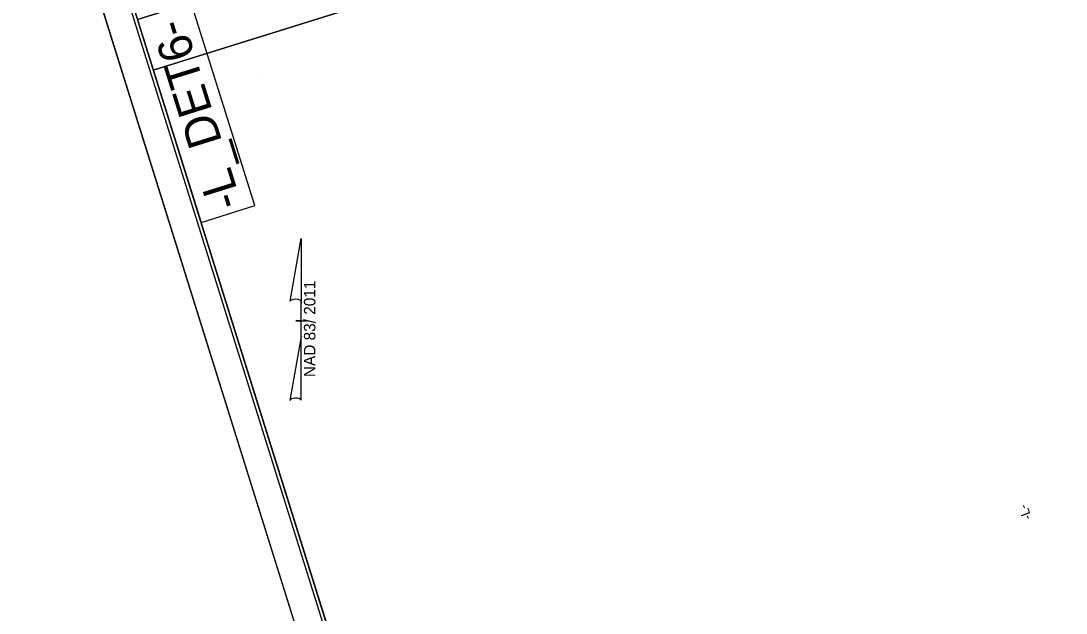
# Model space of a CAD drawing. Extents: x 473667 to 478950, y 494687 to 505998.
# Drawn here: x 473667 to 474441, y 505031 to 505469 of the extents above; entities that cross this region are included whole.
import ezdxf

# ---------------------------------------------------------------- set-up
doc = ezdxf.new("R2010")
doc.units = 0
for name, color, linetype in [('Old_Level_1', 7, 'Continuous'), ('Prop Grid Mask', 7, 'Continuous'), ('Prop Horizontal Alignment Tick Label', 7, 'Continuous'), ('Prop North Arrow NAD83 for Plan Sheets CELL', 7, 'Continuous'), ('Sheet Cutting Line CELL', 7, 'Continuous'), ('Sheet Layout Plan Border', 7, 'Continuous'), ('Sheet North Arrow Point CELL', 7, 'Continuous'), ('Sheet Plan CELL', 7, 'Continuous'), ('Sheet Plan Layout CELL', 7, 'Continuous'), ('Sheet Plot Border Inside CELL', 7, 'Continuous'), ('Sheet Plot Border Outside CELL', 7, 'Continuous')]:
    doc.layers.add(name, color=color, linetype=linetype)

msp = doc.modelspace()

# ---------------------------------------------------------------- linework, layer by layer
at = {"layer": 'Prop Grid Mask'}
msp.add_lwpolyline([(473753.52, 505469.97), (473800.56, 505319.8), (473840.36, 505332.27), (473793.32, 505482.44)], close=True, dxfattribs=at)
at = {"layer": 'Prop North Arrow NAD83 for Plan Sheets CELL'}
for p, q in [((473866.51, 505261.59), (473874.71, 505307.94)), ((473874.76, 505307.94), (473874.71, 505307.94)), ((473874.76, 505307.94), (473874.71, 505307.94)), ((473874.76, 505307.94), (473874.76, 505260.14)), ((473874.76, 505235.34), (473874.76, 505261.54)), ((473874.76, 505260.14), (473874.76, 505261.49)), ((473870.76, 505246.94), (473870.71, 505246.94)), ((473874.31, 505246.94), (473870.76, 505246.94)), ((473870.81, 505246.94), (473878.81, 505246.94)), ((473874.76, 505235.34), (473866.41, 505188.09)), ((473874.81, 505188.29), (473874.76, 505235.34))]:
    msp.add_line(p, q, dxfattribs=at)
for centre, start_param, end_param in [((473870.64, 505261.09), 0.216388, 2.908219), ((473870.64, 505187.92), 0.201328, 3.141593)]:
    msp.add_ellipse(centre, major_axis=(4.23, -0.03), ratio=0.461098, start_param=start_param, end_param=end_param, dxfattribs=at)
at = {"layer": 'Sheet Cutting Line CELL'}
msp.add_line((473667.17, 505670.37), (474170.46, 504063.86), dxfattribs=at)
at = {"layer": 'Sheet Layout Plan Border'}
msp.add_lwpolyline([(474406.84, 504597.01), (474903.65, 504485.25), (475129.18, 504591.08), (474710.64, 505927.06), (474746.68, 505812.01), (474670.33, 505788.09), (474619.34, 505950.85), (473859.33, 505712.76), (473919.13, 505521.87), (473753.52, 505469.97), (474127.2, 504277.17)], close=True, dxfattribs=at)
at = {"layer": 'Sheet North Arrow Point CELL'}
msp.add_line((473843.47, 505426.82), (473843.47, 505426.82), dxfattribs=at)
at = {"layer": 'Sheet Plan CELL'}
for points in [[(473693.71, 505660.9), (474142.15, 504229.46), (475144.13, 504543.36), (474695.69, 505974.78)], [(475144.13, 504543.36), (474142.18, 504229.44), (473753.51, 505469.97), (473896.7, 505514.84), (473836.91, 505705.74), (474695.69, 505974.78)]]:
    msp.add_lwpolyline(points, close=True, dxfattribs=at)
at = {"layer": 'Sheet Plan Layout CELL'}
for points in [[(474142.18, 504229.44), (475144.13, 504543.36), (474695.7, 505974.76), (473895.53, 505724.09), (473967.06, 505495.78), (473765.24, 505432.55)], [(473967.06, 505495.78), (473895.53, 505724.11), (473693.7, 505660.91), (473765.24, 505432.55)]]:
    msp.add_lwpolyline(points, close=True, dxfattribs=at)
at = {"layer": 'Sheet Plot Border Inside CELL'}
msp.add_lwpolyline([(475192.41, 504397.64), (474694.35, 505987.44), (473687.6, 505672.06), (474185.66, 504082.25)], close=True, dxfattribs=at)
at = {"layer": 'Sheet Plot Border Outside CELL'}
msp.add_lwpolyline([(475215.38, 504391.22), (474712.1, 505997.73), (473667.17, 505670.37), (474170.46, 504063.86)], close=True, dxfattribs=at)

# ---------------------------------------------------------------- texts
at = {"layer": 'Old_Level_1'}
msp.add_text('-L_DET6-', height=25, rotation=107.39476, dxfattribs=at).set_placement((473830.87, 505333.55))
at = {"layer": 'Prop Horizontal Alignment Tick Label'}
msp.add_text('-L-', height=7, rotation=110.30214, dxfattribs=at).set_placement((474416.04, 505101.15))
at = {"layer": 'Prop North Arrow NAD83 for Plan Sheets CELL'}
msp.add_text('NAD 83/ 2011', height=8.5, rotation=90, dxfattribs=at).set_placement((473885.28, 505205.42))

doc.saveas('drawing.dxf')
